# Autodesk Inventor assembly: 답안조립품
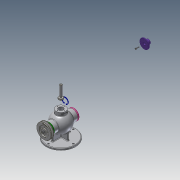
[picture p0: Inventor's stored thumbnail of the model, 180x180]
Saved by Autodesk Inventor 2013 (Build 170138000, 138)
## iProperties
Created: 2020-08
Part Number: 답안조립품
Document SubType Name: Assembly
Designer: user
Author: user
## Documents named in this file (18)
- C:\Users\user\Desktop\700806V1009\답안조립품.iam
- C:\Users\user\Desktop\700806V1009\본체.ipt
- C:\Users\user\Desktop\700806V1009\Ű 3x3x12.ipt
- C:\Users\user\Desktop\700806V1009\V-벨트풀리.ipt
- C:\Users\user\Desktop\700806V1009\너트 M8.ipt
- C:\Users\user\Desktop\700806V1009\뒤커버.ipt
- C:\Users\user\Desktop\700806V1009\멈춤링 15x1.ipt
- C:\Users\user\Desktop\700806V1009\멈춤링 35x1.6.ipt
- 멈춤링 35x1.6.ipt
- C:\Users\user\Desktop\700806V1009\베어링 6202.ipt
- 베어링 6202.ipt
- C:\Users\user\Desktop\700806V1009\볼트 M4.ipt
- C:\Users\user\Desktop\700806V1009\상부커버.ipt
- C:\Users\user\Desktop\700806V1009\슬라이드.ipt
- C:\Users\user\Desktop\700806V1009\앞커버.ipt
- C:\Users\user\Desktop\700806V1009\오일 실 15 30 7.ipt
- C:\Users\user\Desktop\700806V1009\칼라.ipt
- C:\Users\user\Desktop\700806V1009\편심축.ipt
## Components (2 placed, 2 different names)
1. Ű 3x3x12:1
2. V-벨트풀리:1
